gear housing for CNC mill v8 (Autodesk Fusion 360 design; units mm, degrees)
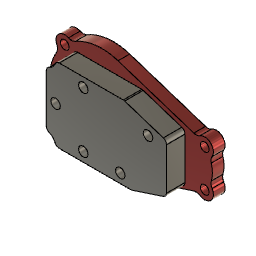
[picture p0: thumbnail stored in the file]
description: Gear Housing Assembly
derived_base_feature "Derived Base Feature1"
derived_base_feature "Derived Base Feature1" bodies "Front Housing"
derived_base_feature "Derived Base Feature1" bodies "Front Cover"
derived_base_feature "Derived Base Feature1" bodies "Back Housing"
as_built_joint "As-built1"
offset_faces "OffsetFaces1" distance 5
delete_face "DeleteFace1"
delete_face "DeleteFace2"
sketch "Sketch1" plane through (0, -21, 0) normal (0, -1, 0) x axis (1, 0, 0)
  line L1 (11.1724, 34.2225) -> (63.2283, 17.2281)
  line L2 (63.2283, -17.2281) -> (11.1724, -34.2225)
  arc A1 centre (64.7801, 21.9812) radius 5 clockwise from (67.4836, 17.7752) to (63.2283, 17.2281)
  arc A2 centre (0, 0) radius 36 clockwise from (-18.189, 31.067) to (11.1724, 34.2225)
  arc A3 centre (-20.7152, 35.3819) radius 5 clockwise from (-18.189, 31.067) to (-22.8701, 30.8701)
  arc A4 centre (-25.4558, 25.4558) radius 6 clockwise from (-30.8701, 22.8701) to (-22.8701, 30.8701)
  arc A5 centre (-35.3819, 20.7152) radius 5 clockwise from (-30.8701, 22.8701) to (-31.067, 18.189)
  arc A6 centre (0, 0) radius 36 clockwise from (-31.067, -18.189) to (-31.067, 18.189)
  arc A7 centre (-35.3819, -20.7152) radius 5 clockwise from (-31.067, -18.189) to (-30.8701, -22.8701)
  arc A8 centre (-25.4558, -25.4558) radius 6 clockwise from (-22.8701, -30.8701) to (-30.8701, -22.8701)
  arc A9 centre (-20.7152, -35.3819) radius 5 clockwise from (-22.8701, -30.8701) to (-18.189, -31.067)
  arc A10 centre (0, 0) radius 36 clockwise from (11.1724, -34.2225) to (-18.189, -31.067)
  arc A11 centre (64.7801, -21.9812) radius 5 clockwise from (63.2283, -17.2281) to (67.4836, -17.7752)
  arc A12 centre (70.7279, -12.7279) radius 6 clockwise from (75.774, -9.4818) to (67.4836, -17.7752)
  arc A13 centre (79.979, -6.7767) radius 5 clockwise from (75.774, -9.4818) to (75.201, -5.3035)
  arc A14 centre (58, 0) radius 18 clockwise from (75.201, 5.3035) to (75.201, -5.3035)
  arc A15 centre (79.979, 6.7767) radius 5 clockwise from (75.201, 5.3035) to (75.774, 9.4818)
  arc A16 centre (70.7279, 12.7279) radius 6 clockwise from (67.4836, 17.7752) to (75.774, 9.4818)
  circle C1 centre (70.7279, -12.7279) radius 3
  circle C2 centre (70.7279, 12.7279) radius 3
  circle C3 centre (-25.4558, -25.4558) radius 3
  circle C4 centre (-25.4558, 25.4558) radius 3
  circle C5 centre (0, 0) radius 5.25
  circle C6 centre (0, 0) radius 19.05
  point P1 (0, 0)
  point P34 (0, 0)
  point P35 (0, -19.05)
  point P36 (-19.05, 0)
  point P37 (0, 19.05)
  point P38 (44.45, 12.7)
  point P39 (25.4, -19.05)
  coincident P1 P34
  coincident C6 P35
  coincident C6 P36
  coincident C6 P37
  vertical P34 P35
  horizontal P1 P36
  vertical P1 P37
  dimension "d2" diameter C6 = 38.1
  dimension "d3" distance P1 P38 = 44.45
  dimension "d4" distance P1 P38 = 12.7
  dimension "d5" distance P34 P39 = 25.4
  dimension "d6" distance P34 P39 = 19.05
hole "Hole1" HoleDepth 5.715 HoleDiameter 5.1308 TipAngle 118
ground "Ground1"
ground "Ground2"
ground "Ground3"
ground "Ground4"
position "Position1"
sketch "Sketch1" plane through (0, 0, 0) normal (0, 1, 0) x axis (1, 0, 0)
  line L1 (57.15, -25.4) -> (-25.4, -25.4)
  line L2 (57.15, 25.4) -> (57.15, -25.4)
  line L3 (-25.4, 25.4) -> (57.15, 25.4)
  line L4 (-25.4, -25.4) -> (-25.4, 25.4)
  line L5 (11.1724, -34.2225) -> (63.2283, -17.2281)
  line L6 (63.2283, 17.2281) -> (11.1724, 34.2225)
  line L7 (10.1871, -31.2042) -> (62.243, -14.2098)
  line L8 (62.7357, 15.719) -> (10.6797, 32.7134)
  circle C1 centre (-25.4558, -25.4558) radius 3
  circle C2 centre (-25.4558, 25.4558) radius 3
  circle C3 centre (-25.4558, -25.4558) radius 6.35
  circle C4 centre (-25.4558, 25.4558) radius 6.35
  point P1 (0, 0)
  horizontal L1
  vertical L2
  horizontal L3
  vertical L4
  concentric C1 C3
  concentric C2 C4
  equal C3 C4
  dimension "d10" distance P1 L1 = 25.4
  dimension "d11" distance P1 L3 = 25.4 (= "d10")
  dimension "d12" distance P1 L2 = 57.15
  dimension "d13" distance P1 L4 = 25.4
  dimension "d14" diameter C3 = 12.7
  dimension "d15" = 3.175
  dimension "d16" = 1.5875
extrude "Extrude1" new body sketch "Sketch1" profile of L1 L2 L3 L4 C3 C4 L7 L8 against normal blind 12.7
fillet "Fillet1" radius 3.175
hole "Hole1" HoleDepth 12.7 HoleDiameter 6.477 TipAngle 118
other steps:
thread "Thread1"
create_component "CreateComponent1"
create_component "CreateComponent5"
create_component "CreateComponent1"
create_component "CreateComponent2"
create_component "CreateComponent3"
named bodies: "Back Housing", "Front Cover", "Front Housing"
